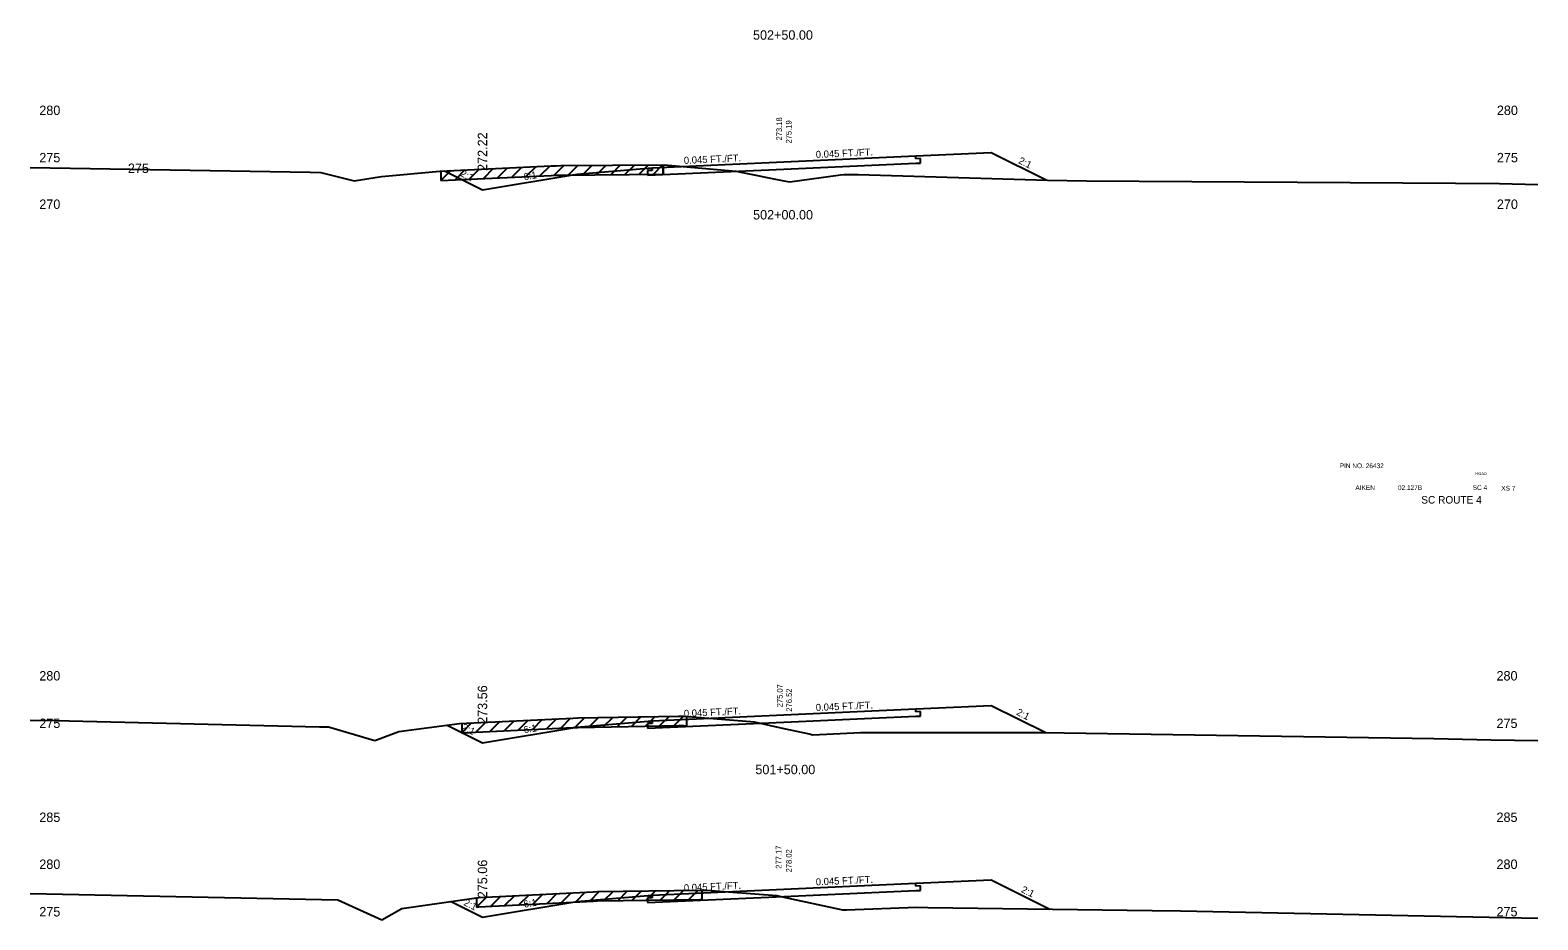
# Model space of a CAD drawing. Extents: x 883 to 1160, y 1002 to 4323.
# Drawn here: x 1000 to 1160, y 1744.8 to 1839.2 of the extents above; entities that cross this region are included whole.
import ezdxf

# ---------------------------------------------------------------- set-up
doc = ezdxf.new("R2010")
doc.units = 0
for name, color, linetype in [('Level 1', 7, 'Continuous'), ('Level 10', 7, 'Continuous'), ('Level 11', 7, 'Continuous'), ('Level 12', 7, 'Continuous'), ('Level 3', 7, 'Continuous'), ('Level 32', 7, 'Continuous'), ('Level 33', 7, 'Continuous'), ('Level 59', 7, 'Continuous'), ('Level 6', 7, 'Continuous'), ('Level 60', 7, 'Continuous'), ('Level 61', 7, 'Continuous'), ('Level 7', 7, 'Continuous')]:
    doc.layers.add(name, color=color, linetype=linetype)

msp = doc.modelspace()

# ---------------------------------------------------------------- linework, layer by layer
at = {"layer": 'Level 11'}
for p, q in [((1094, 1825.52), (1094, 1825.82)), ((1094.5, 1825.54), (1094, 1825.52)), ((1094, 1825.04), (1094.5, 1825.06)), ((1094.5, 1825.06), (1094.5, 1825.54)), ((1094, 1766.85), (1094, 1767.15)), ((1094.5, 1766.87), (1094, 1766.85)), ((1094.5, 1766.39), (1094.5, 1766.87)), ((1094, 1766.37), (1094.5, 1766.39)), ((1094, 1748.35), (1094, 1748.65)), ((1094.5, 1748.37), (1094, 1748.35)), ((1094, 1747.87), (1094.5, 1747.89)), ((1094.5, 1747.89), (1094.5, 1748.37))]:
    msp.add_line(p, q, dxfattribs=at)
at = {"layer": 'Level 12'}
for p, q in [((1065.5, 1823.78), (1080, 1824.41)), ((1066, 1824.26), (1065.5, 1824.26)), ((1065.5, 1824.26), (1065.5, 1823.78)), ((1066, 1824.56), (1066, 1824.26)), ((1067.19, 1824.86), (1067.19, 1823.83)), ((1080, 1824.41), (1094, 1825.04)), ((1065.5, 1765.11), (1080, 1765.74)), ((1066, 1765.59), (1065.5, 1765.59)), ((1065.5, 1765.59), (1065.5, 1765.11)), ((1066, 1765.89), (1066, 1765.59)), ((1080, 1765.74), (1094, 1766.37)), ((1065.5, 1746.61), (1080, 1747.24)), ((1066, 1747.39), (1066, 1747.09)), ((1080, 1747.24), (1094, 1747.87)), ((1066, 1747.09), (1065.5, 1747.09)), ((1065.5, 1747.09), (1065.5, 1746.61))]:
    msp.add_line(p, q, dxfattribs=at)
at = {"layer": 'Level 59'}
for p, q in [((1080, 1825.19), (1094, 1825.82)), ((1066, 1824.56), (1080, 1825.19)), ((1066, 1765.89), (1080, 1766.52)), ((1080, 1766.52), (1094, 1767.15)), ((1066, 1747.39), (1080, 1748.02)), ((1080, 1748.02), (1094, 1748.65))]:
    msp.add_line(p, q, dxfattribs=at)
at = {"layer": 'Level 6'}
for p, q in [((1094, 1825.82), (1102, 1826.18)), ((1058, 1823.89), (1066, 1824.56)), ((1094, 1767.15), (1102, 1767.51)), ((1058, 1765.22), (1066, 1765.89)), ((1094, 1748.65), (1102, 1749.01)), ((1058, 1746.72), (1066, 1747.39))]:
    msp.add_line(p, q, dxfattribs=at)
at = {"layer": 'Level 60'}
for p, q in [((1000, 1824.59), (1004.24, 1824.52)), ((1004.24, 1824.52), (1029.72, 1824.1)), ((1029.72, 1824.1), (1030.86, 1824.06)), ((1030.86, 1824.06), (1034.39, 1823.17)), ((1037.28, 1823.64), (1043.49, 1824.21)), ((1043.49, 1824.21), (1055.3, 1824.75)), ((1055.3, 1824.75), (1055.83, 1824.77)), ((1055.83, 1824.77), (1056.31, 1824.78)), ((1056.31, 1824.78), (1067.27, 1824.86)), ((1067.27, 1824.86), (1074.49, 1824.24)), ((1074.49, 1824.24), (1074.91, 1824.21)), ((1074.91, 1824.21), (1075.25, 1824.13)), ((1075.25, 1824.13), (1080, 1823.18)), ((1034.39, 1823.17), (1037.28, 1823.64)), ((1080, 1823.18), (1080.63, 1823.05)), ((1080.63, 1823.05), (1086, 1823.82)), ((1086, 1823.82), (1086.38, 1823.84)), ((1086.38, 1823.84), (1087.87, 1823.83)), ((1087.87, 1823.83), (1107.95, 1823.23)), ((1107.95, 1823.23), (1112.09, 1823.17)), ((1112.09, 1823.17), (1151.26, 1822.93)), ((1151.26, 1822.93), (1155.94, 1822.87)), ((1155.94, 1822.87), (1160, 1822.79)), ((1000, 1765.97), (1002.64, 1765.91)), ((1002.64, 1765.91), (1030.7, 1765.26)), ((1030.7, 1765.26), (1031.67, 1765.24)), ((1031.67, 1765.24), (1036.58, 1763.79)), ((1039.13, 1764.75), (1045.58, 1765.61)), ((1045.58, 1765.61), (1057.64, 1766.17)), ((1057.64, 1766.17), (1058.11, 1766.19)), ((1058.11, 1766.19), (1068.82, 1766.37)), ((1068.82, 1766.37), (1069.37, 1766.38)), ((1069.37, 1766.38), (1076.44, 1765.8)), ((1076.44, 1765.8), (1076.84, 1765.77)), ((1076.84, 1765.77), (1080, 1765.07)), ((1080, 1765.07), (1082.66, 1764.49)), ((1036.58, 1763.79), (1039.13, 1764.75)), ((1082.66, 1764.49), (1083.05, 1764.4)), ((1083.05, 1764.4), (1088.12, 1764.63)), ((1088.12, 1764.63), (1088.57, 1764.64)), ((1088.57, 1764.64), (1107.64, 1764.63)), ((1107.64, 1764.63), (1109.73, 1764.6)), ((1109.73, 1764.6), (1148.97, 1763.99)), ((1148.97, 1763.99), (1155.04, 1763.86)), ((1155.04, 1763.86), (1160, 1763.79)), ((1000, 1747.57), (1032.64, 1746.89)), ((1047.61, 1747.14), (1059.75, 1747.75)), ((1059.75, 1747.75), (1060.2, 1747.77)), ((1060.2, 1747.77), (1071.08, 1747.92)), ((1071.08, 1747.92), (1071.78, 1747.9)), ((1071.78, 1747.9), (1079.25, 1747.34)), ((1079.25, 1747.34), (1080, 1747.17)), ((1032.64, 1746.89), (1037.32, 1744.77)), ((1037.32, 1744.77), (1039.46, 1745.97)), ((1039.46, 1745.97), (1047.61, 1747.14)), ((1080, 1747.17), (1085.9, 1745.9)), ((1085.9, 1745.9), (1086.21, 1745.82)), ((1086.21, 1745.82), (1086.64, 1745.82)), ((1086.64, 1745.82), (1094.11, 1746.1)), ((1094.11, 1746.1), (1095.27, 1746.08)), ((1095.27, 1746.08), (1119.07, 1745.76)), ((1119.07, 1745.76), (1122.07, 1745.71)), ((1122.07, 1745.71), (1160, 1744.94))]:
    msp.add_line(p, q, dxfattribs=at)
at = {"layer": 'Level 61'}
for p, q in [((1044.64, 1824.26), (1043.59, 1823.22)), ((1043.59, 1824.22), (1043.59, 1823.22)), ((1046.14, 1824.33), (1045.09, 1823.29)), ((1047.64, 1824.4), (1046.6, 1823.35)), ((1049.14, 1824.47), (1048.1, 1823.42)), ((1050.65, 1824.54), (1049.6, 1823.49)), ((1052.15, 1824.6), (1051.1, 1823.56)), ((1053.65, 1824.67), (1052.6, 1823.62)), ((1055.15, 1824.74), (1054.1, 1823.69)), ((1056.62, 1824.78), (1055.6, 1823.76)), ((1058.11, 1824.79), (1057.1, 1823.78)), ((1059.61, 1824.8), (1058.6, 1823.8)), ((1061.11, 1824.81), (1060.1, 1823.81)), ((1062.61, 1824.83), (1061.61, 1823.82)), ((1064.12, 1824.84), (1063.11, 1823.83)), ((1065.62, 1824.85), (1064.61, 1823.84)), ((1067.12, 1824.86), (1066.11, 1823.85)), ((1067.19, 1823.86), (1067.19, 1824.86)), ((1043.59, 1823.22), (1055.3, 1823.75)), ((1055.3, 1823.75), (1055.83, 1823.77)), ((1055.83, 1823.77), (1056.31, 1823.78)), ((1056.31, 1823.78), (1067.19, 1823.86)), ((1046.85, 1765.66), (1045.8, 1764.62)), ((1045.8, 1765.62), (1045.8, 1764.62)), ((1045.8, 1764.62), (1057.64, 1765.17)), ((1048.35, 1765.73), (1047.3, 1764.69)), ((1049.85, 1765.8), (1048.8, 1764.76)), ((1051.35, 1765.87), (1050.3, 1764.83)), ((1052.85, 1765.94), (1051.8, 1764.89)), ((1054.35, 1766.01), (1053.3, 1764.96)), ((1055.85, 1766.08), (1054.8, 1765.03)), ((1057.35, 1766.15), (1056.3, 1765.1)), ((1057.64, 1765.17), (1058.11, 1765.19)), ((1058.83, 1766.2), (1057.8, 1765.17)), ((1058.11, 1765.19), (1068.82, 1765.37)), ((1060.32, 1766.23), (1059.3, 1765.21)), ((1061.82, 1766.25), (1060.8, 1765.23)), ((1063.32, 1766.28), (1062.3, 1765.26)), ((1064.82, 1766.3), (1063.8, 1765.29)), ((1066.32, 1766.33), (1065.3, 1765.31)), ((1067.82, 1766.35), (1066.8, 1765.34)), ((1069.32, 1766.38), (1068.31, 1765.36)), ((1068.82, 1765.37), (1069.37, 1765.38)), ((1069.37, 1765.38), (1069.7, 1765.35)), ((1069.7, 1765.35), (1069.7, 1766.35)), ((1049.9, 1747.25), (1048.85, 1746.2)), ((1051.4, 1747.33), (1050.35, 1746.28)), ((1052.91, 1747.4), (1051.85, 1746.35)), ((1054.41, 1747.48), (1053.35, 1746.43)), ((1055.91, 1747.56), (1054.85, 1746.5)), ((1057.41, 1747.63), (1056.35, 1746.58)), ((1058.91, 1747.71), (1057.86, 1746.65)), ((1060.4, 1747.77), (1059.36, 1746.73)), ((1061.87, 1747.79), (1060.86, 1746.78)), ((1063.37, 1747.81), (1062.36, 1746.8)), ((1064.87, 1747.84), (1063.86, 1746.82)), ((1066.38, 1747.86), (1065.36, 1746.84)), ((1067.88, 1747.88), (1066.86, 1746.86)), ((1069.38, 1747.9), (1068.36, 1746.88)), ((1070.88, 1747.92), (1069.86, 1746.9)), ((1071.32, 1746.91), (1071.32, 1747.91)), ((1048.43, 1747.18), (1047.35, 1746.1)), ((1047.35, 1747.1), (1047.35, 1746.1)), ((1047.35, 1746.1), (1047.61, 1746.14)), ((1047.61, 1746.14), (1059.75, 1746.75)), ((1059.75, 1746.75), (1060.2, 1746.77)), ((1060.2, 1746.77), (1071.08, 1746.92)), ((1071.08, 1746.92), (1071.32, 1746.91))]:
    msp.add_line(p, q, dxfattribs=at)
at = {"layer": 'Level 7'}
for p, q in [((1102, 1826.18), (1107.88, 1823.24)), ((1043.98, 1824.23), (1048, 1822.22)), ((1048, 1822.22), (1058, 1823.89)), ((1102, 1767.51), (1107.77, 1764.63)), ((1044.26, 1765.43), (1048, 1763.56)), ((1048, 1763.56), (1058, 1765.22)), ((1102, 1749.01), (1108.21, 1745.9)), ((1044.68, 1746.72), (1048, 1745.06)), ((1048, 1745.06), (1058, 1746.72))]:
    msp.add_line(p, q, dxfattribs=at)

# ---------------------------------------------------------------- texts
at = {"layer": 'Level 1'}
for s, height, p in [('502+50.00', 1, (1076.71, 1838.14)), ('502+00.00', 1, (1076.72, 1819.07)), ('PIN NO. 26432', 0.5, (1138.97, 1792.69)), ('AIKEN', 0.5, (1140.64, 1790.37)), ('02.127B', 0.5, (1145.15, 1790.37)), ('SC 4', 0.5, (1153.09, 1790.37)), ('XS 7', 0.5, (1156.12, 1790.31)), ('SC ROUTE 4', 0.8, (1147.63, 1788.93)), ('501+50.00', 1, (1076.96, 1760.22))]:
    msp.add_text(s, height=height, dxfattribs=at).set_placement(p)
at = {"layer": 'Level 10'}
for s, p in [('273.18', (1079.79, 1827.45)), ('275.07', (1079.85, 1767.32)), ('277.17', (1079.73, 1750.19))]:
    msp.add_text(s, height=0.6, rotation=90, dxfattribs=at).set_placement(p)
at = {"layer": 'Level 3'}
for s, height, p in [(' 280', 1, (1000.6, 1830.15)), (' 280', 1, (1155.28, 1830.15)), (' 275', 1, (1000.6, 1825.13)), (' 275', 1, (1155.28, 1825.13)), (' 275', 1, (1010, 1824)), (' 270', 1, (1000.6, 1820.19)), (' 270', 1, (1155.28, 1820.19)), ('ROAD', 0.3, (1153.38, 1791.96)), (' 280', 1, (1000.6, 1770.16)), (' 280', 1, (1155.24, 1770.16)), (' 275', 1, (1000.6, 1765.12)), (' 275', 1, (1155.24, 1765.12)), (' 285', 1, (1000.6, 1755.15)), (' 285', 1, (1155.24, 1755.15)), (' 280', 1, (1000.6, 1750.17)), (' 280', 1, (1155.24, 1750.17)), (' 275', 1, (1000.6, 1745.13)), (' 275', 1, (1155.24, 1745.13))]:
    msp.add_text(s, height=height, dxfattribs=at).set_placement(p)
at = {"layer": 'Level 32'}
for s, rotation, p in [('0.045 FT./FT.', 2.5766, (1069.39, 1824.96)), ('0.045 FT./FT.', 2.5766, (1083.39, 1825.59)), ('2:1', 333.435, (1104.81, 1825.07)), ('2:1', 333.435, (1045.59, 1823.71)), ('6:1', 9.4623, (1052.43, 1823.22)), ('0.045 FT./FT.', 2.5766, (1069.39, 1766.29)), ('0.045 FT./FT.', 2.5766, (1083.39, 1766.92)), ('2:1', 333.435, (1104.59, 1766.56)), ('2:1', 333.435, (1045.73, 1764.97)), ('6:1', 9.4623, (1052.43, 1764.55)), ('0.045 FT./FT.', 2.5766, (1069.39, 1747.79)), ('0.045 FT./FT.', 2.5766, (1083.39, 1748.42)), ('2:1', 333.435, (1105.1, 1747.74)), ('2:1', 333.435, (1045.94, 1746.36)), ('6:1', 9.4623, (1052.43, 1746.05))]:
    msp.add_text(s, height=0.75, rotation=rotation, dxfattribs=at).set_placement(p)
at = {"layer": 'Level 33'}
for s, p in [('272.22', (1048.5, 1824.22)), ('273.56', (1048.5, 1765.56)), ('275.06', (1048.5, 1747.06))]:
    msp.add_text(s, height=1, rotation=90, dxfattribs=at).set_placement(p)
at = {"layer": 'Level 59'}
for s, p in [(' 275.19', (1080.8, 1826.91)), (' 276.52', (1080.84, 1766.63)), (' 278.02', (1080.82, 1749.58))]:
    msp.add_text(s, height=0.6, rotation=90, dxfattribs=at).set_placement(p)

doc.saveas('drawing.dxf')
